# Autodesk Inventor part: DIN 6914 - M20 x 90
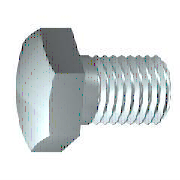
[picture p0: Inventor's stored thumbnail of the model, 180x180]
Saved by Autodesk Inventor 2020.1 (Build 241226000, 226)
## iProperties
Manager: www.cadconsulting.pl
Company: Fabian Stasiak CAD Consulting
Created: 2006-02
Part Number: DIN 6914 - M20 x 90
Material: Stal, miękka
Description: Śruba
Document SubType Name: Modeling
Standard: DIN 6914
Designer: F.Stasiak
Standards Organization: DIN
Language: pl-PL
Size Designation: M20 x 90
Categories: <MemberInstance><Categories><Category DisplayName="Mocowania" InternalName="e4da775c-781d-43d5-af7c-5136215cf5a6" Mnemonic="FSTN"><Category DisplayName="Śruby"
Density: 7.85 g/cm^3
Appearance: Stal
Mass: 311.058 g
Surface Area: 87.6185 cm^2
Volume: 39.6253 cm^3
Author: F.Stasiak
Subject: Zbiór ćwiczeń. Autodesk Inventor 2020. Kurs podstawowy
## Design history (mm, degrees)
sketch "Szkic1"
  geometry: L1 (0, 15)-(0, 10); L2 (57, 10)-(90, 10); L3 (90, 10)-(90, 0); L4 (90, 0)-(-0.4, 0); L5 (-9.44, 0)-(117.12, 0) reference; L6 (-0.4, 0)-(-0.4, 15); L7 (-0.4, 15)-(0, 15); L8 (57, 10)-(55.466, 10); L9 (55.466, 10)-(0, 10); L10 (0, -1.5)-(0, 19.5) reference
  constraints: 16 end point, 2 collinear, 2 perpendicular, 1 parallel
  dimensions: "d0" = 90 distance between parallel lines of L3 L1 (= NLG); "d1" = 33 distance from line of L2.start L3 (= GEL); "d2" = 20 diameter of L2 L4 (= GD); "d9" = 0.4001 distance between parallel lines of L6 L1 (computed from SD); "d10" = 30 diameter of L7 L4 (= SD2); "d13" = 1.53373 distance of L2.start L8.end (computed from GAL); "d14" = 20 diameter of L9 L4 (= BDM)
revolve "Bryła" sketch "Szkic1" stored, may be unused: angle "d12" = 90 deg
sketch "Szkic2"
  geometry: L1 (0, 18.475)-(16, 9.238); L2 (16, 9.238)-(16, -9.238); L3 (16, -9.238)-(0, -18.475); L4 (0, -18.475)-(-16, -9.238); L5 (-16, -9.238)-(-16, 9.238); L6 (-16, 9.238)-(0, 18.475); 2 further points
  constraints: 12 end point, 1 coincident, 1 vertical, 11 other
  dimensions: "d11" = 32 distance between parallel lines of L5 L2 (= SW)
extrude "Głowica" join sketch "Szkic2" distance "d3" = 12.6 (= KOH - SD); taper "d4" = 0 deg
sketch "Szkic4"
  geometry: L1 (-13, 16)-(-13, 18.475); L2 (-13, 18.475)-(-11.571, 18.475); L3 (-11.571, 18.475)-(-13, 16); L4 (-14.26, 0)-(3.38, 0) reference; L5 (-0.4, 18.475)-(-13, 18.475) reference; L6 (-13, 9.238)-(-13, 18.475) reference
  constraints: 6 end point, 2 collinear, 1 perpendicular, 1 vertical
  dimensions: "d5" = 30 deg angle of L3 L1 (= ANG1); "d19" = 32 diameter of L1.start L4 (= SW0)
revolve "Faza1" sketch "Szkic4" stored, may be unused: angle "d21" = 90 deg
workplane "Work Plane1"
node "Bryła1"
node "Korpusy bryłowe"
node "Korpusy powierzchniowe"
feature "Gwint" dims "d15" = 33 (= GEL), "d16" = 0
chamfer "Faza2" distance "d6" = 1.53363 (= -0.5 x SPD + 0.5 x GD); stored, may be unused: second distance "d7" = 1.53373 (computed from GUL), angle "d55" = 45 deg
other parameters: "NLG" = 90 [user parameter; used in 1 equation term], "GD" = 20 (= NND) [user parameter; used in 2 equation terms], "BDM" = 20 (= NND) [user parameter; used in 1 equation term], "KOH" = 13 [user parameter; used in 1 equation term], "GEL" = 33 [user parameter; used in 2 equation terms], "SW" = 32 [user parameter; used in 3 equation terms], "SW0" = 32 (= SW) [user parameter; used in 1 equation term], "SPD" = 16.93275 (= NND - 1.2269 x PTC) [user parameter; used in 1 equation term], "SD2" = 30 (= SDH) [user parameter; used in 1 equation term], "SD" = 0.4 [user parameter; used in 2 equation terms], "ANG1" = 30 deg [user parameter; used in 1 equation term], "GAL" = 1.53363 (= 0.61345 x PTC) [user parameter; used in 1 equation term], "GUL" = 1.53363 (= 0.61345 x PTC) [user parameter; used in 1 equation term], "d8" = 0, "RR" = 1.5 [user parameter], "d57" = 0, "d58" = 0, "TPU" = 4 (computed from PTC) [user parameter], "WFT" = 0.4 [user parameter], "GD1" = 16.93275 (= THREADDIA - 1.2269 x PTC) [user parameter], "TOA" = 30 deg [user parameter], "FAWI" = 45 deg [user parameter], "PTC" = 2.5 [user parameter; used in 5 equation terms], "E0" = 36.96 (= 1.155 x SW) [user parameter]
